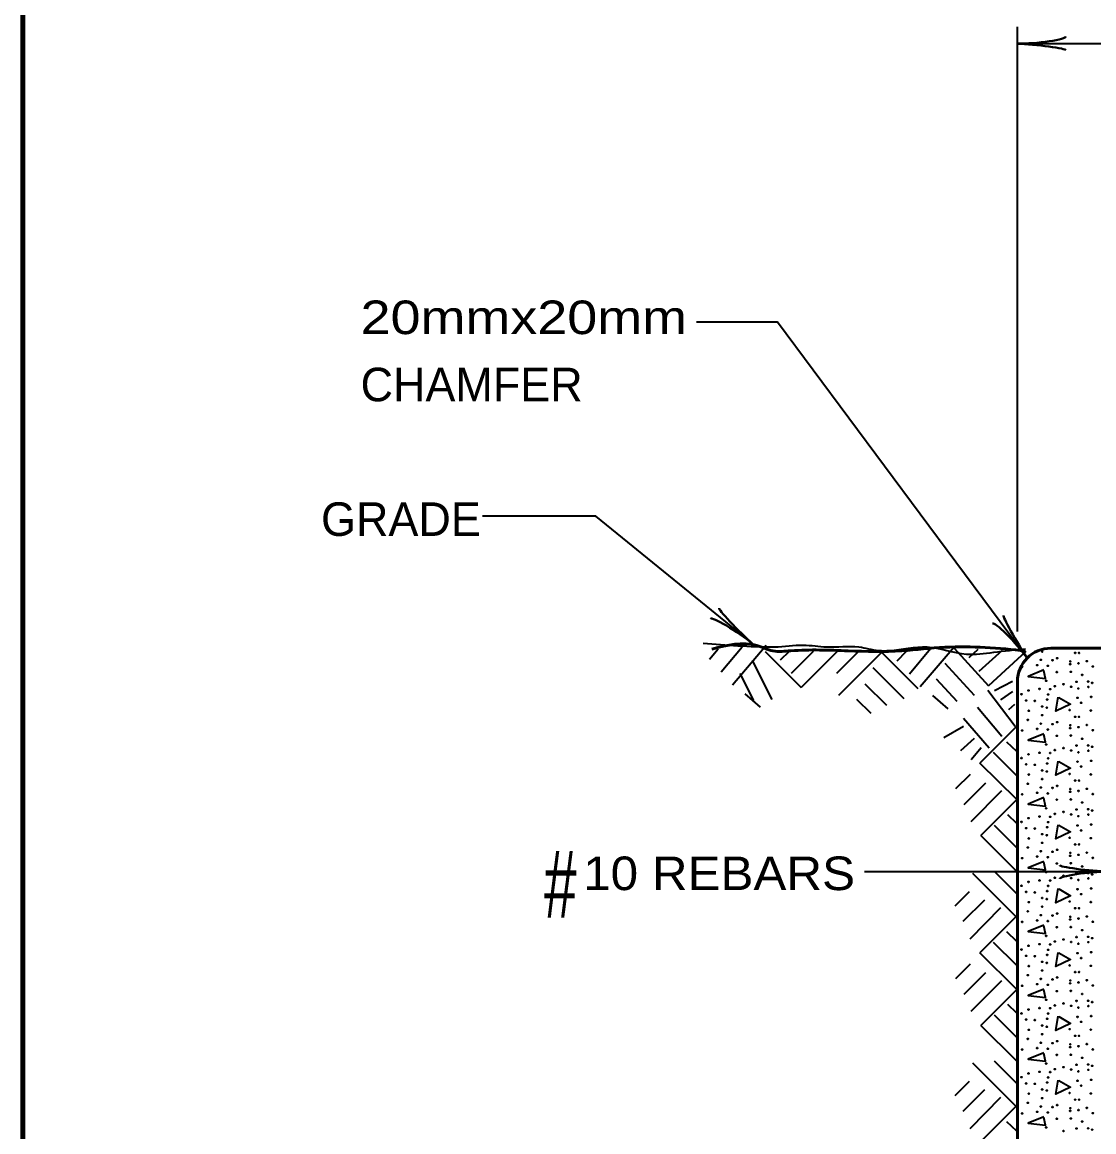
# Model space of a CAD drawing. Extents: x 442 to 1297, y -1132 to -588.
# Drawn here: x 499 to 575.6, y -918.8 to -839.5 of the extents above; entities that cross this region are included whole.
import ezdxf
from ezdxf.enums import TextEntityAlignment as Align

# ---------------------------------------------------------------- set-up
doc = ezdxf.new("R2010")
doc.units = 0
doc.header["$LTSCALE"] = 0.96
doc.layers.add('1', color=7, linetype='Continuous', lineweight=35)

msp = doc.modelspace()

# ---------------------------------------------------------------- linework, layer by layer
at = {"layer": '1'}
for p, q in [((570.1476, -883.0076), (570.1476, -839.8076)), ((570.1476, -841.0076), (675.7476, -841.0076)), ((552.1915, -884.007), (549.7944, -886.8473)), ((548.7704, -884.2808), (548.1561, -885.0282)), ((550.4929, -884.143), (548.9743, -885.9258)), ((552.1273, -884.4442), (554.6953, -887.0122)), ((553.8313, -884.4442), (553.2073, -885.0682)), ((555.5593, -884.4442), (553.9753, -886.0282)), ((557.2633, -884.4442), (554.6953, -887.0122)), ((558.7993, -884.4442), (557.2153, -886.0282)), ((560.5033, -884.4442), (557.3593, -887.5882)), ((560.3833, -884.4442), (563.0233, -887.0842)), ((562.2073, -884.4442), (561.5353, -885.1402)), ((563.9308, -884.2525), (562.438, -886.057)), ((565.6302, -884.1406), (563.2113, -886.9623)), ((565.6257, -884.2171), (568.0771, -886.8966)), ((567.328, -884.2928), (566.6769, -884.8884)), ((569.0543, -884.3695), (567.4015, -885.8816)), ((570.7566, -884.4452), (568.0771, -886.8966)), ((551.207, -885.0937), (552.603, -887.8868)), ((559.8073, -885.5962), (562.0393, -887.8042)), ((564.9544, -885.2683), (567.0621, -887.5722)), ((550.3189, -886.0119), (551.29, -887.9549)), ((564.3517, -886.3946), (565.818, -887.9973)), ((559.2553, -886.7482), (560.7913, -888.2842)), ((568.5062, -887.235), (569.794, -886.5558)), ((550.6633, -887.476), (551.7744, -888.4224)), ((558.6553, -887.8522), (559.6873, -888.8602)), ((564.0753, -887.5977), (565.179, -888.5526)), ((569.9813, -889.8114), (568.0379, -887.235)), ((568.9745, -887.8908), (569.8174, -887.3053)), ((569.0447, -890.514), (567.2887, -888.4529)), ((569.5364, -888.5934), (569.9578, -888.2187)), ((568.1316, -891.3572), (566.3053, -889.2258)), ((566.3053, -889.8114), (564.9004, -890.6077)), ((570.0996, -889.7756), (567.4596, -892.4156)), ((567.0545, -890.6545), (566.0711, -891.5446)), ((570.0996, -891.5996), (569.4036, -890.9276)), ((567.5696, -891.3338), (566.8438, -892.177)), ((570.0996, -893.3276), (568.4436, -891.6716)), ((570.0996, -895.0316), (567.4596, -892.4156)), ((566.7636, -893.2316), (565.7316, -894.2636)), ((567.8676, -893.8556), (566.3316, -895.3916)), ((569.0196, -894.4076), (566.8116, -896.6156)), ((570.0996, -895.0316), (567.5316, -897.5996)), ((570.0996, -896.7356), (569.4756, -896.1116)), ((570.0996, -898.4636), (568.5156, -896.8796)), ((570.0996, -900.1676), (567.5316, -897.5996)), ((576.6313, -900.1912), (559.2216, -900.1912)), ((570.0996, -903.4556), (566.9556, -900.3116)), ((570.0996, -901.7516), (568.5156, -900.1676)), ((566.6916, -901.6076), (565.6836, -902.6396)), ((567.7956, -902.2076), (566.2596, -903.7436)), ((568.9476, -902.7596), (566.7396, -904.9916)), ((570.0996, -903.3356), (567.4596, -905.9756)), ((570.0996, -905.1596), (569.4036, -904.4876)), ((570.0996, -906.8876), (568.4436, -905.2316)), ((570.0996, -908.5916), (567.4596, -905.9756)), ((566.7636, -906.7916), (565.7316, -907.8236)), ((567.8676, -907.4156), (566.3316, -908.9516)), ((569.0196, -907.9676), (566.8116, -910.1756)), ((570.0996, -908.5916), (567.5316, -911.1596)), ((570.0996, -910.2956), (569.4756, -909.6716)), ((570.0996, -912.0236), (568.5156, -910.4396)), ((570.0996, -913.7276), (567.5316, -911.1596)), ((570.0996, -917.0156), (566.9556, -913.8716)), ((570.0996, -915.3116), (568.5156, -913.7276)), ((566.6916, -915.1676), (565.6836, -916.1996)), ((567.7956, -915.7676), (566.2596, -917.3036)), ((568.9476, -916.3196), (566.7396, -918.5516)), ((570.0996, -916.8956), (567.4596, -919.5356)), ((570.0996, -918.7196), (569.4036, -918.0476))]:
    msp.add_line(p, q, dxfattribs=at)
at = {"layer": '1', "lineweight": 53}
for p, q in [((577.3476, -884.2076), (572.5476, -884.2076)), ((570.1476, -886.6076), (570.1476, -980.7675)), ((570.1476, -886.6076), (570.1476, -980.5452))]:
    msp.add_line(p, q, dxfattribs=at)
at = {"layer": '1', "lineweight": 158}
msp.add_lwpolyline([(1290.7447, -594.0679), (499.0447, -594.1679), (499.1447, -1120.1679)], dxfattribs=at)
at = {"layer": '1'}
for points in [[(570.8505, -884.9105), (553.0157, -860.9018), (547.2288, -860.9018)], [(551.2197, -883.8839), (540.0285, -874.7707), (531.9336, -874.7707)], [(572.0414, -885.7667), (570.9134, -886.2227), (572.1614, -886.3667), (572.0414, -885.8147)], [(573.0974, -887.7347), (573.9374, -888.2147), (572.9054, -888.7187), (573.0494, -887.7107)], [(570.1476, -888.4022), (570.1694, -888.4067), (570.1476, -888.4301)], [(572.0414, -890.3267), (570.9134, -890.7827), (572.1614, -890.9267), (572.0414, -890.3747)], [(573.0974, -892.2947), (573.9374, -892.7747), (572.9054, -893.2787), (573.0494, -892.2707)], [(570.1476, -892.9622), (570.1694, -892.9667), (570.1476, -892.9901)], [(572.0414, -894.8867), (570.9134, -895.3427), (572.1614, -895.4867), (572.0414, -894.9347)], [(570.1476, -897.5222), (570.1694, -897.5267), (570.1476, -897.5501)], [(573.0974, -896.8547), (573.9374, -897.3347), (572.9054, -897.8387), (573.0494, -896.8307)], [(572.0414, -899.4467), (570.9134, -899.9027), (572.1614, -900.0467), (572.0414, -899.4947)], [(573.0974, -901.4147), (573.9374, -901.8947), (572.9054, -902.3987), (573.0494, -901.3907)], [(570.1476, -902.0822), (570.1694, -902.0867), (570.1476, -902.1101)], [(572.0414, -904.0067), (570.9134, -904.4627), (572.1614, -904.6067), (572.0414, -904.0547)], [(573.0974, -905.9747), (573.9374, -906.4547), (572.9054, -906.9587), (573.0494, -905.9507)], [(570.1476, -906.6422), (570.1694, -906.6467), (570.1476, -906.6701)], [(572.0414, -908.5667), (570.9134, -909.0227), (572.1614, -909.1667), (572.0414, -908.6147)], [(573.0974, -910.5347), (573.9374, -911.0147), (572.9054, -911.5187), (573.0494, -910.5107)], [(570.1476, -911.2022), (570.1694, -911.2067), (570.1476, -911.2301)], [(572.0414, -913.1267), (570.9134, -913.5827), (572.1614, -913.7267), (572.0414, -913.1747)], [(573.0974, -915.0947), (573.9374, -915.5747), (572.9054, -916.0787), (573.0494, -915.0707)], [(570.1476, -915.7622), (570.1694, -915.7667), (570.1476, -915.7901)], [(572.0414, -917.6867), (570.9134, -918.1427), (572.1614, -918.2867), (572.0414, -917.7347)]]:
    msp.add_lwpolyline(points, dxfattribs=at)
for centre in [(574.2786, -884.5496), (574.5489, -884.5496), (571.559, -885.4187), (571.8135, -885.0427), (572.3224, -885.4665), (572.6564, -885.0745), (572.9904, -884.9314), (573.9128, -885.3551), (573.9287, -885.1541), (574.5171, -885.2915), (575.1055, -885.1381), (575.5441, -885.5141), (572.9585, -885.9119), (573.9605, -885.896), (574.7716, -886.1186), (570.9388, -887.2323), (571.7181, -887.1209), (572.1951, -886.5323), (572.4814, -887.1368), (572.8154, -886.9301), (573.4515, -886.7868), (573.9923, -886.9618), (574.3739, -886.6118), (574.5013, -887.0891), (575.201, -886.5959), (575.2168, -886.9777), (575.4805, -886.6914), (570.4458, -887.5027), (570.7797, -887.9482), (571.3999, -887.98), (572.2747, -887.8845), (572.3542, -887.5186), (574.4375, -887.7572), (575.4077, -887.6936), (570.9705, -888.68), (571.9089, -888.3778), (572.2588, -888.4573), (573.8809, -888.6323), (574.708, -888.1073), (575.3841, -888.6668), (570.8911, -889.3322), (571.8135, -889.6027), (571.9248, -888.9982), (572.9904, -889.4914), (574.2786, -889.1096), (574.5489, -889.1096), (570.4934, -890.0901), (571.559, -889.9787), (572.3224, -890.0265), (572.6564, -889.6345), (573.9128, -889.9151), (573.9287, -889.7141), (574.5171, -889.8515), (575.1055, -889.6981), (575.5441, -890.0741), (572.1951, -891.0923), (572.9585, -890.4719), (573.9605, -890.456), (574.3739, -891.1718), (574.7716, -890.6786), (575.201, -891.1559), (570.9388, -891.7923), (571.7181, -891.6809), (572.4814, -891.6968), (572.8154, -891.4901), (573.4515, -891.3468), (573.9923, -891.5218), (574.5013, -891.6491), (575.2168, -891.5377), (575.4805, -891.2514), (570.4458, -892.0627), (570.7797, -892.5082), (571.3999, -892.54), (572.2747, -892.4445), (572.3542, -892.0786), (574.4375, -892.3172), (574.708, -892.6673), (575.4077, -892.2536), (570.9705, -893.24), (571.9089, -892.9378), (571.9248, -893.5582), (572.2588, -893.0173), (573.8809, -893.1923), (575.3841, -893.2268), (570.8911, -893.8922), (571.8135, -894.1627), (572.6564, -894.1945), (572.9904, -894.0514), (573.9287, -894.2741), (574.2786, -893.6696), (574.5489, -893.6696), (575.1055, -894.2581), (570.4934, -894.6501), (571.559, -894.5387), (572.3224, -894.5865), (572.9585, -895.0319), (573.9128, -894.4751), (573.9605, -895.016), (574.5171, -894.4115), (575.5441, -894.6341), (572.1951, -895.6523), (573.4515, -895.9068), (574.3739, -895.7318), (574.7716, -895.2386), (575.201, -895.7159), (575.4805, -895.8114), (570.4458, -896.6227), (570.9388, -896.3523), (571.7181, -896.2409), (572.3542, -896.6386), (572.4814, -896.2568), (572.8154, -896.0501), (573.9923, -896.0818), (574.5013, -896.2091), (575.2168, -896.0977), (570.7797, -897.0682), (571.3999, -897.1), (571.9089, -897.4978), (572.2747, -897.0045), (574.4375, -896.8772), (574.708, -897.2273), (575.4077, -896.8136), (570.9705, -897.8), (571.9248, -898.1182), (572.2588, -897.5773), (573.8809, -897.7523), (574.2786, -898.2296), (574.5489, -898.2296), (575.3841, -897.7868), (570.8911, -898.4522), (571.559, -899.0987), (571.8135, -898.7227), (572.6564, -898.7545), (572.9904, -898.6114), (573.9128, -899.0351), (573.9287, -898.8341), (574.5171, -898.9715), (575.1055, -898.8181), (570.4934, -899.2101), (572.3224, -899.1465), (572.9585, -899.5919), (573.9605, -899.576), (574.7716, -899.7986), (575.5441, -899.1941), (572.1951, -900.2123), (572.8154, -900.6101), (573.4515, -900.4668), (573.9923, -900.6418), (574.3739, -900.2918), (575.201, -900.2759), (575.2168, -900.6577), (575.4805, -900.3714), (570.4458, -901.1827), (570.9388, -900.9123), (571.7181, -900.8009), (572.3542, -901.1986), (572.4814, -900.8168), (574.4375, -901.4372), (574.5013, -900.7691), (575.4077, -901.3736), (570.7797, -901.6282), (571.3999, -901.66), (571.9089, -902.0578), (572.2588, -902.1373), (572.2747, -901.5645), (573.8809, -902.3123), (574.708, -901.7873), (570.8911, -903.0122), (570.9705, -902.36), (571.9248, -902.6782), (574.2786, -902.7896), (574.5489, -902.7896), (575.3841, -902.3468), (570.4934, -903.7701), (571.559, -903.6587), (571.8135, -903.2827), (572.3224, -903.7065), (572.6564, -903.3145), (572.9904, -903.1714), (573.9128, -903.5951), (573.9287, -903.3941), (574.5171, -903.5315), (575.1055, -903.3781), (575.5441, -903.7541), (572.9585, -904.1519), (573.9605, -904.136), (574.7716, -904.3586), (570.9388, -905.4723), (571.7181, -905.3609), (572.1951, -904.7723), (572.4814, -905.3768), (572.8154, -905.1701), (573.4515, -905.0268), (573.9923, -905.2018), (574.3739, -904.8518), (574.5013, -905.3291), (575.201, -904.8359), (575.2168, -905.2177), (575.4805, -904.9314), (570.4458, -905.7427), (570.7797, -906.1882), (571.3999, -906.22), (572.2747, -906.1245), (572.3542, -905.7586), (574.4375, -905.9972), (575.4077, -905.9336), (570.9705, -906.92), (571.9089, -906.6178), (572.2588, -906.6973), (573.8809, -906.8723), (574.708, -906.3473), (575.3841, -906.9068), (570.8911, -907.5722), (571.8135, -907.8427), (571.9248, -907.2382), (572.9904, -907.7314), (574.2786, -907.3496), (574.5489, -907.3496), (570.4934, -908.3301), (571.559, -908.2187), (572.3224, -908.2665), (572.6564, -907.8745), (573.9128, -908.1551), (573.9287, -907.9541), (574.5171, -908.0915), (575.1055, -907.9381), (575.5441, -908.3141), (572.1951, -909.3323), (572.9585, -908.7119), (573.9605, -908.696), (574.3739, -909.4118), (574.7716, -908.9186), (575.201, -909.3959), (570.9388, -910.0323), (571.7181, -909.9209), (572.4814, -909.9368), (572.8154, -909.7301), (573.4515, -909.5868), (573.9923, -909.7618), (574.5013, -909.8891), (575.2168, -909.7777), (575.4805, -909.4914), (570.4458, -910.3027), (570.7797, -910.7482), (571.3999, -910.78), (572.2747, -910.6845), (572.3542, -910.3186), (574.4375, -910.5572), (574.708, -910.9073), (575.4077, -910.4936), (570.9705, -911.48), (571.9089, -911.1778), (571.9248, -911.7982), (572.2588, -911.2573), (573.8809, -911.4323), (575.3841, -911.4668), (570.8911, -912.1322), (571.8135, -912.4027), (572.6564, -912.4345), (572.9904, -912.2914), (573.9287, -912.5141), (574.2786, -911.9096), (574.5489, -911.9096), (575.1055, -912.4981), (570.4934, -912.8901), (571.559, -912.7787), (572.3224, -912.8265), (572.9585, -913.2719), (573.9128, -912.7151), (573.9605, -913.256), (574.5171, -912.6515), (575.5441, -912.8741), (572.1951, -913.8923), (573.4515, -914.1468), (574.3739, -913.9718), (574.7716, -913.4786), (575.201, -913.9559), (575.4805, -914.0514), (570.4458, -914.8627), (570.9388, -914.5923), (571.7181, -914.4809), (572.3542, -914.8786), (572.4814, -914.4968), (572.8154, -914.2901), (573.9923, -914.3218), (574.5013, -914.4491), (575.2168, -914.3377), (570.7797, -915.3082), (571.3999, -915.34), (571.9089, -915.7378), (572.2747, -915.2445), (574.4375, -915.1172), (574.708, -915.4673), (575.4077, -915.0536), (570.9705, -916.04), (571.9248, -916.3582), (572.2588, -915.8173), (573.8809, -915.9923), (574.2786, -916.4696), (574.5489, -916.4696), (575.3841, -916.0268), (570.8911, -916.6922), (571.559, -917.3387), (571.8135, -916.9627), (572.6564, -916.9945), (572.9904, -916.8514), (573.9128, -917.2751), (573.9287, -917.0741), (574.5171, -917.2115), (575.1055, -917.0581), (570.4934, -917.4501), (572.3224, -917.3865), (572.9585, -917.8319), (573.9605, -917.816), (574.7716, -918.0386), (575.5441, -917.4341), (572.1951, -918.4523), (573.4515, -918.7068), (574.3739, -918.5318), (575.201, -918.5159), (575.4805, -918.6114)]:
    msp.add_circle(centre, 0.0318, dxfattribs=at)
at = {"layer": '1', "lineweight": 53}
msp.add_arc((572.5476, -886.6076), 2.4, 90, 180, dxfattribs=at)
at = {"layer": '1'}
for centre, start, end in [((571.9248, -884.4382), 149.88234, 66.65391), ((570.4934, -885.5301), 275.38651, 14.22226)]:
    msp.add_arc(centre, 0.0318, start, end, dxfattribs=at)
at = {"layer": '1', "lineweight": 40}
for centre, major_axis, ratio, start_param, end_param in [((571.503, -841.2712), (-2.1077, 0.2108), 0.07063, 3.1407148, 5.41811), ((571.4678, -840.6857), (-2.1428, -0.1874), 0.122415, 0.8963533, 3.1415927), ((550.3374, -882.838), (1.5013, -1.4944), 0.07063, 3.1407148, 5.41811), ((549.995, -883.3142), (1.7799, -1.2078), 0.122415, 0.8963533, 3.1415927), ((569.8035, -884.0571), (1.4282, -1.6084), 0.122415, 0.8963533, 3.1415927), ((570.2525, -883.6797), (1.0877, -1.8177), 0.07063, 3.1407148, 5.41811), ((575.2759, -899.9276), (2.1077, -0.2108), 0.07063, 3.1407148, 5.41811), ((575.3111, -900.5131), (2.1428, 0.1874), 0.122415, 0.8963533, 3.1415927)]:
    msp.add_ellipse(centre, major_axis=major_axis, ratio=ratio, start_param=start_param, end_param=end_param, dxfattribs=at)
at = {"layer": '1'}
msp.add_spline([(570.7348, -884.2681), (568.4301, -884.5243), (566.5095, -884.6524), (563.6926, -884.14), (561.0037, -884.3962), (560.2354, -884.3962), (558.827, -884.14), (556.5223, -884.14), (554.8577, -884.0119), (552.8091, -884.14), (552.681, -884.14), (547.6874, -883.8839)], degree=3, dxfattribs=at)
at = {"layer": '1', "lineweight": 53}
msp.add_spline([(570.7348, -884.3962), (564.973, -884.14), (561.9, -884.3962), (558.0587, -884.3962), (553.9614, -884.3962), (552.681, -884.3962), (551.5287, -884.0119), (548.3276, -884.2681)], degree=3, dxfattribs=at)

# ---------------------------------------------------------------- texts
at = {"layer": '1'}
for s, width, p in [('20mmx20mm', 1.2, (523.2203, -861.7676)), ('10 REBARS', 1.1, (539.1234, -901.495))]:
    msp.add_text(s, height=2.4, dxfattribs=dict(at, width=width)).set_placement(p)
for s, p in [('CHAMFER', (523.2203, -866.5676)), ('GRADE', (520.3962, -876.1866))]:
    msp.add_text(s, height=2.4, dxfattribs=at).set_placement(p)
at = {"layer": '1', "width": 0.65}
msp.add_text('#', height=4.8, dxfattribs=at).set_placement((537.4912, -903.4721), align=Align.CENTER)

doc.saveas('drawing.dxf')
